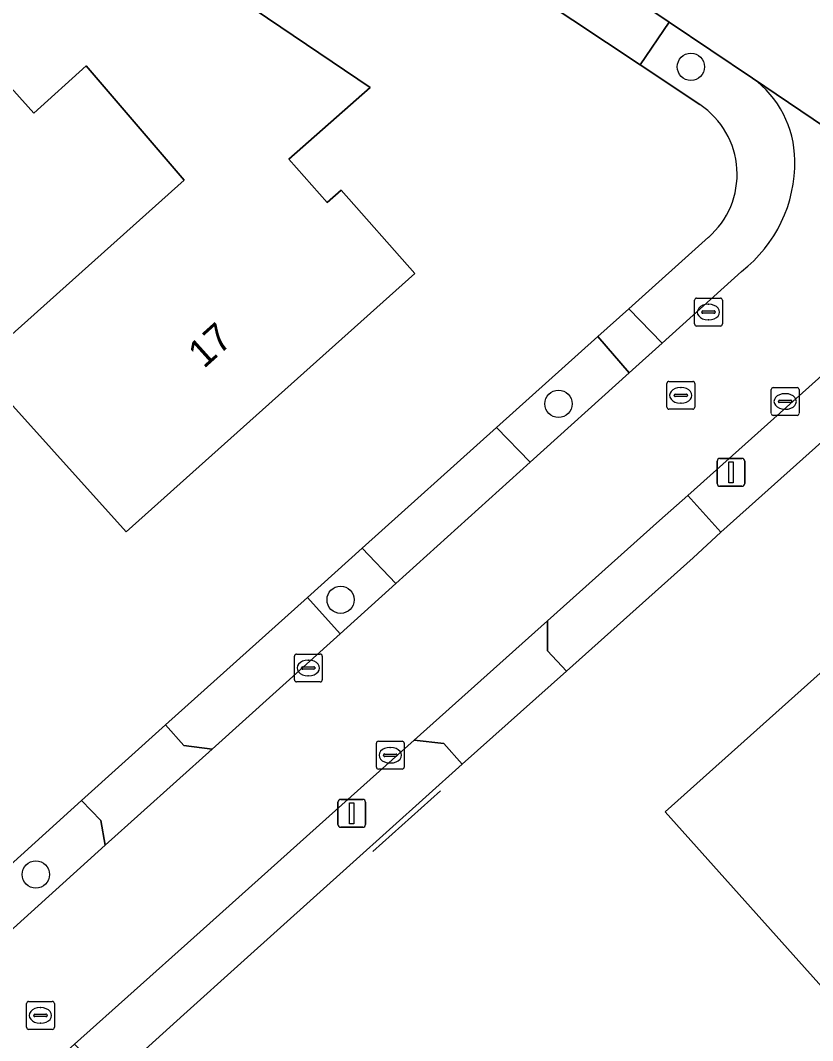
# Model space of a CAD drawing. Extents: x 163266 to 164362, y 381528 to 382286.
# Drawn here: x 163999.37 to 164027.8, y 381843.46 to 381880.07 of the extents above; entities that cross this region are included whole.
import ezdxf

# ---------------------------------------------------------------- set-up
doc = ezdxf.new("R2010")
doc.units = 0
for name, color, linetype in [('IMGEO_Boom', 7, 'Continuous'), ('IMGEO_Erf', 7, 'Continuous'), ('IMGEO_Groenvoorziening', 7, 'Continuous'), ('IMGEO_Hek', 7, 'Continuous'), ('IMGEO_Kolk', 7, 'Continuous'), ('IMGEO_Lichtmast', 7, 'Continuous'), ('IMGEO_Pand', 7, 'Continuous'), ('IMGEO_Pand_nummerreeks', 7, 'Continuous'), ('IMGEO_Rijbaan_lokaal_open', 7, 'Continuous'), ('IMGEO_Rioolput', 7, 'Continuous'), ('IMGEO_Voetpad_halfverhard', 7, 'Continuous'), ('IMGEO_Voetpad_open', 7, 'Continuous')]:
    doc.layers.add(name, color=color, linetype=linetype)

msp = doc.modelspace()

# ---------------------------------------------------------------- linework, layer by layer
at = {"layer": 'IMGEO_Boom'}
for centre in [(164023.434, 381878.405), (164018.683, 381866.309), (164010.865, 381859.278), (163999.93, 381849.416)]:
    msp.add_circle(centre, 0.489, dxfattribs=at)
at = {"layer": 'IMGEO_Erf'}
for points in [[(164023.757, 381877.048), (164021.609, 381878.481), (164017.994, 381880.891), (164016.88, 381881.641), (164004.426, 381889.991), (164000.285, 381892.756), (163999.021, 381893.687), (163929.416, 381832.861), (163943.921, 381816.693), (163948.755, 381811.304)], [(163995.657, 381846.77), (163996.816, 381847.775), (164001.565, 381852.077), (164004.578, 381854.784), (164009.675, 381859.363), (164011.636, 381861.124), (164016.456, 381865.455), (164020.095, 381868.724), (164021.208, 381869.724), (164024.059, 381872.285)], [(164032.089, 381868.482), (164024.506, 381861.698), (164023.513, 381860.781), (164018.964, 381856.717), (164015.222, 381853.377), (164011.317, 381849.862), (164007.28, 381846.23), (164005.236, 381844.39), (164002.603, 381842.006), (163996.129, 381836.145), (163993.15, 381833.516), (163988.909, 381829.691), (163987.827, 381828.705), (163977.86, 381819.863), (163977.933, 381819.715), (163968.392, 381811.087), (163967.388, 381810.18), (163960.895, 381804.406)]]:
    msp.add_lwpolyline(points, dxfattribs=at)
for points in [[(164003.17, 381861.72), (163997.803, 381867.67), (164005.249, 381874.338), (164001.739, 381878.437), (163999.856, 381876.747), (163995.833, 381881.231), (164000.469, 381885.413), (164011.921, 381877.668), (164009.01, 381875.086), (164010.379, 381873.532), (164010.889, 381873.982), (164013.525, 381870.99)], [(164022.506, 381851.666), (164034.418, 381862.323), (164040.335, 381855.737), (164028.428, 381845.055)]]:
    msp.add_lwpolyline(points, close=True, dxfattribs=at)
msp.add_arc((164022.092, 381874.551), 3.001, 310.9517, 56.3043, dxfattribs=at)
at = {"layer": 'IMGEO_Groenvoorziening'}
for points in [[(164025.646, 381878.003), (164022.652, 381880.012), (164021.609, 381878.481), (164023.757, 381877.048)], [(164024.059, 381872.285), (164021.208, 381869.724), (164022.399, 381868.488), (164025.25, 381871.061)], [(164030.291, 381869.269), (164023.318, 381863.024), (164024.506, 381861.698), (164032.089, 381868.482)]]:
    msp.add_lwpolyline(points, dxfattribs=at)
for points in [[(164020.095, 381868.724), (164016.456, 381865.455), (164017.67, 381864.218), (164021.224, 381867.427)], [(164012.841, 381859.859), (164011.636, 381861.124), (164009.675, 381859.363), (164010.847, 381858.058)], [(164002.418, 381850.471), (164002.258, 381851.352), (164001.565, 381852.077), (163996.816, 381847.775), (163997.98, 381846.456)]]:
    msp.add_lwpolyline(points, close=True, dxfattribs=at)
for centre, radius, start, end in [((164023.475, 381875.024), 3.686, 0.5272, 53.9182), ((164022.092, 381874.551), 3.001, 310.9517, 56.3043), ((164022.214, 381874.968), 4.948, 307.8517, 1.0426)]:
    msp.add_arc(centre, radius, start, end, dxfattribs=at)
at = {"layer": 'IMGEO_Hek'}
msp.add_lwpolyline([(164012.02, 381850.245), (164014.445, 381852.423)], dxfattribs=at)
at = {"layer": 'IMGEO_Kolk'}
for p, q in [((164023.563, 381869.176), (164023.563, 381870.028)), ((164023.638, 381870.102), (164024.49, 381870.102)), ((164024.564, 381870.028), (164024.564, 381869.176)), ((164023.865, 381869.645), (164024.263, 381869.645)), ((164024.051, 381869.882), (164024.076, 381869.882)), ((164023.822, 381869.596), (164023.822, 381869.608)), ((164024.26, 381869.559), (164023.862, 381869.559)), ((164024.074, 381869.322), (164024.049, 381869.322)), ((164024.306, 381869.608), (164024.306, 381869.596)), ((164024.49, 381869.102), (164023.638, 381869.102)), ((164026.315, 381865.968), (164026.315, 381866.82)), ((164026.39, 381866.894), (164027.242, 381866.894)), ((164027.316, 381866.82), (164027.316, 381865.968)), ((164026.574, 381866.388), (164026.574, 381866.4)), ((164027.012, 381866.351), (164026.614, 381866.351)), ((164026.617, 381866.437), (164027.015, 381866.437)), ((164026.803, 381866.674), (164026.828, 381866.674)), ((164027.058, 381866.4), (164027.058, 381866.388)), ((164026.826, 381866.114), (164026.801, 381866.114)), ((164027.242, 381865.894), (164026.39, 381865.894)), ((164009.206, 381856.402), (164009.206, 381857.254)), ((164009.281, 381857.328), (164010.133, 381857.328)), ((164010.207, 381857.254), (164010.207, 381856.402)), ((164009.465, 381856.822), (164009.465, 381856.834)), ((164009.508, 381856.871), (164009.906, 381856.871)), ((164009.694, 381857.108), (164009.719, 381857.108)), ((164009.949, 381856.834), (164009.949, 381856.822)), ((164009.903, 381856.785), (164009.505, 381856.785)), ((164009.717, 381856.548), (164009.692, 381856.548)), ((164010.133, 381856.328), (164009.281, 381856.328)), ((164012.147, 381853.272), (164012.147, 381854.124)), ((164012.222, 381854.198), (164013.074, 381854.198)), ((164012.635, 381853.978), (164012.66, 381853.978)), ((164013.148, 381854.124), (164013.148, 381853.272)), ((164012.406, 381853.692), (164012.406, 381853.704)), ((164012.844, 381853.655), (164012.446, 381853.655)), ((164012.449, 381853.741), (164012.847, 381853.741)), ((164012.89, 381853.704), (164012.89, 381853.692)), ((164013.074, 381853.198), (164012.222, 381853.198)), ((164012.658, 381853.418), (164012.633, 381853.418))]:
    msp.add_line(p, q, dxfattribs=at)
for points in [[(164023.563, 381869.176), (164023.563, 381870.028)], [(164023.638, 381870.102), (164024.49, 381870.102)], [(164024.564, 381870.028), (164024.564, 381869.176)], [(164024.49, 381869.102), (164023.638, 381869.102)], [(164026.315, 381865.968), (164026.315, 381866.82)], [(164026.39, 381866.894), (164027.242, 381866.894)], [(164027.316, 381866.82), (164027.316, 381865.968)], [(164027.242, 381865.894), (164026.39, 381865.894)], [(164009.206, 381856.402), (164009.206, 381857.254)], [(164009.281, 381857.328), (164010.133, 381857.328)], [(164010.207, 381857.254), (164010.207, 381856.402)], [(164010.133, 381856.328), (164009.281, 381856.328)], [(164012.147, 381853.272), (164012.147, 381854.124)], [(164012.222, 381854.198), (164013.074, 381854.198)], [(164013.148, 381854.124), (164013.148, 381853.272)], [(164013.074, 381853.198), (164012.222, 381853.198)]]:
    msp.add_lwpolyline(points, dxfattribs=at)
for centre, radius, start, end in [((164023.64, 381870.026), 0.0765, 91.552, 178.448), ((164023.64, 381870.026), 0.0765, 91.552, 178.448), ((164024.488, 381870.026), 0.0765, 1.552, 88.448), ((164024.488, 381870.026), 0.0765, 1.552, 88.448), ((164023.862, 381869.605), 0.0403, 85.8775, 175.7526), ((164024.267, 381869.607), 0.0386, 1.7309, 96.639), ((164023.859, 381869.595), 0.0366, 178.938, 274.7102), ((164024.263, 381869.602), 0.043, 264.8664, 352.4533), ((164023.64, 381869.178), 0.0765, 181.552, 268.448), ((164023.64, 381869.178), 0.0765, 181.552, 268.448), ((164024.488, 381869.178), 0.0765, 271.552, 358.448), ((164024.488, 381869.178), 0.0765, 271.552, 358.448), ((164026.392, 381866.818), 0.0765, 91.552, 178.448), ((164026.392, 381866.818), 0.0765, 91.552, 178.448), ((164027.24, 381866.818), 0.0765, 1.552, 88.448), ((164027.24, 381866.818), 0.0765, 1.552, 88.448), ((164026.614, 381866.397), 0.0403, 85.8775, 175.7526), ((164026.611, 381866.387), 0.0366, 178.938, 274.7102), ((164027.015, 381866.394), 0.043, 264.8664, 352.4533), ((164027.019, 381866.399), 0.0386, 1.7309, 96.639), ((164026.392, 381865.97), 0.0765, 181.552, 268.448), ((164026.392, 381865.97), 0.0765, 181.552, 268.448), ((164027.24, 381865.97), 0.0765, 271.552, 358.448), ((164027.24, 381865.97), 0.0765, 271.552, 358.448), ((164009.283, 381857.252), 0.0765, 91.552, 178.448), ((164009.283, 381857.252), 0.0765, 91.552, 178.448), ((164010.131, 381857.252), 0.0765, 1.552, 88.448), ((164010.131, 381857.252), 0.0765, 1.552, 88.448), ((164009.505, 381856.831), 0.0403, 85.8775, 175.7526), ((164009.91, 381856.833), 0.0386, 1.7309, 96.639), ((164009.502, 381856.821), 0.0366, 178.938, 274.7102), ((164009.906, 381856.828), 0.043, 264.8664, 352.4533), ((164009.283, 381856.404), 0.0765, 181.552, 268.448), ((164009.283, 381856.404), 0.0765, 181.552, 268.448), ((164010.131, 381856.404), 0.0765, 271.552, 358.448), ((164010.131, 381856.404), 0.0765, 271.552, 358.448), ((164012.224, 381854.122), 0.0765, 91.552, 178.448), ((164012.224, 381854.122), 0.0765, 91.552, 178.448), ((164013.072, 381854.122), 0.0765, 1.552, 88.448), ((164013.072, 381854.122), 0.0765, 1.552, 88.448), ((164012.446, 381853.701), 0.0403, 85.8775, 175.7526), ((164012.443, 381853.691), 0.0366, 178.938, 274.7102), ((164012.847, 381853.698), 0.043, 264.8664, 352.4533), ((164012.851, 381853.703), 0.0386, 1.7309, 96.639), ((164012.224, 381853.274), 0.0765, 181.552, 268.448), ((164012.224, 381853.274), 0.0765, 181.552, 268.448), ((164013.072, 381853.274), 0.0765, 271.552, 358.448), ((164013.072, 381853.274), 0.0765, 271.552, 358.448)]:
    msp.add_arc(centre, radius, start, end, dxfattribs=at)
for centre, major_axis, ratio, start_param, end_param in [((164024.05, 381869.602), (-0.387, 0.002), 0.722429, 4.712389, 7.853982), ((164024.075, 381869.602), (-0.39, 0.002), 0.717154, 1.570796, 4.712389), ((164026.802, 381866.394), (-0.387, 0.002), 0.722429, 4.712389, 7.853982), ((164026.827, 381866.394), (-0.39, 0.002), 0.717154, 1.570796, 4.712389), ((164009.693, 381856.828), (-0.387, 0.002), 0.722429, 4.712389, 7.853982), ((164009.718, 381856.828), (-0.39, 0.002), 0.717154, 1.570796, 4.712389), ((164012.634, 381853.698), (-0.387, 0.002), 0.722429, 4.712389, 7.853982), ((164012.659, 381853.698), (-0.39, 0.002), 0.717154, 1.570796, 4.712389)]:
    msp.add_ellipse(centre, major_axis=major_axis, ratio=ratio, start_param=start_param, end_param=end_param, dxfattribs=at)
at = {"layer": 'IMGEO_Lichtmast'}
for p, q in [((164024.376, 381863.449), (164024.376, 381864.249)), ((164024.376, 381864.249), (164024.376, 381863.449)), ((164024.476, 381864.349), (164025.266, 381864.349)), ((164025.266, 381864.349), (164024.476, 381864.349)), ((164025.366, 381864.249), (164025.366, 381863.449)), ((164025.366, 381863.449), (164025.366, 381864.249)), ((164025.266, 381863.349), (164024.476, 381863.349)), ((164024.476, 381863.349), (164025.266, 381863.349)), ((164010.869, 381852.111), (164011.659, 381852.111)), ((164011.659, 381852.111), (164010.869, 381852.111)), ((164010.769, 381851.211), (164010.769, 381852.011)), ((164010.769, 381852.011), (164010.769, 381851.211)), ((164011.759, 381852.011), (164011.759, 381851.211)), ((164011.759, 381851.211), (164011.759, 381852.011)), ((164011.659, 381851.111), (164010.869, 381851.111)), ((164010.869, 381851.111), (164011.659, 381851.111))]:
    msp.add_line(p, q, dxfattribs=at)
for points in [[(164024.796, 381864.224), (164024.946, 381864.224), (164024.946, 381863.474), (164024.796, 381863.474), (164024.796, 381864.224)], [(164011.189, 381851.986), (164011.339, 381851.986), (164011.339, 381851.236), (164011.189, 381851.236), (164011.189, 381851.986)]]:
    msp.add_lwpolyline(points, dxfattribs=at)
for centre, start, end in [((164024.476, 381864.249), 90, 180), ((164024.476, 381864.249), 90, 180), ((164025.266, 381864.249), 0, 90), ((164025.266, 381864.249), 360, 90), ((164024.476, 381863.449), 180, 270), ((164024.476, 381863.449), 180, 270), ((164025.266, 381863.449), 270, 0), ((164025.266, 381863.449), 270, 0), ((164010.869, 381852.011), 90, 180), ((164010.869, 381852.011), 90, 180), ((164011.659, 381852.011), 0, 90), ((164011.659, 381852.011), 360, 90), ((164010.869, 381851.211), 180, 270), ((164010.869, 381851.211), 180, 270), ((164011.659, 381851.211), 270, 0), ((164011.659, 381851.211), 270, 0)]:
    msp.add_arc(centre, 0.1, start, end, dxfattribs=at)
at = {"layer": 'IMGEO_Pand'}
for points in [[(164003.17, 381861.72), (164013.525, 381870.99), (164010.889, 381873.982), (164010.379, 381873.532), (164009.01, 381875.086), (164011.921, 381877.668), (164000.469, 381885.413), (163995.833, 381881.231), (163999.856, 381876.747), (164001.739, 381878.437), (164005.249, 381874.338), (163997.803, 381867.67)], [(164028.428, 381845.055), (164040.335, 381855.737), (164034.418, 381862.323), (164022.506, 381851.666)]]:
    msp.add_lwpolyline(points, close=True, dxfattribs=at)
at = {"layer": 'IMGEO_Rijbaan_lokaal_open'}
for points in [[(163998.571, 381897.023), (163999, 381896.735), (163999.804, 381896.196), (163999.429, 381895.594), (163999.796, 381895.348), (164001.074, 381894.49), (164006.028, 381891.166), (164017.924, 381883.184), (164019.023, 381882.448), (164022.652, 381880.012), (164025.646, 381878.003), (164036.893, 381870.385), (164038.576, 381869.252), (164061.479, 381853.831), (164067.085, 381850.057), (164074.222, 381845.198), (164075.369, 381844.441), (164083.195, 381839.066), (164084.215, 381838.47)], [(164036.893, 381870.385), (164025.646, 381878.003)], [(164025.25, 381871.061), (164022.399, 381868.488), (164021.224, 381867.427), (164017.67, 381864.218), (164012.841, 381859.859), (164010.847, 381858.058), (164006.252, 381853.91), (164002.418, 381850.471), (163997.98, 381846.456), (163996.879, 381845.395), (163993.203, 381842.104), (163989.118, 381838.447), (163984.024, 381833.886), (163978.103, 381828.584), (163977.1, 381827.686), (163974.775, 381825.604), (163971.984, 381823.105), (163967.775, 381819.337), (163963.088, 381815.14), (163962.055, 381814.215), (163958.417, 381810.957), (163956.533, 381809.27)], [(163966.045, 381811.633), (163967.113, 381812.548), (163968.97, 381814.303), (163976.655, 381821.186), (163986.562, 381830.06), (163987.615, 381831.052), (163991.405, 381834.479), (163995.302, 381837.956), (164001.317, 381843.33), (164005.596, 381847.153), (164010.686, 381851.711), (164013.509, 381854.239), (164018.289, 381858.52), (164022.308, 381862.12), (164023.318, 381863.024), (164030.291, 381869.269)]]:
    msp.add_lwpolyline(points, dxfattribs=at)
for centre, radius, start, end in [((164023.475, 381875.024), 3.686, 0.5272, 53.9182), ((164022.214, 381874.968), 4.948, 307.8517, 1.0426)]:
    msp.add_arc(centre, radius, start, end, dxfattribs=at)
at = {"layer": 'IMGEO_Rioolput'}
for p, q in [((164022.645, 381867.115), (164023.497, 381867.115)), ((164022.57, 381866.189), (164022.57, 381867.041)), ((164023.058, 381866.895), (164023.083, 381866.895)), ((164023.571, 381867.041), (164023.571, 381866.189)), ((164022.829, 381866.609), (164022.829, 381866.621)), ((164023.267, 381866.572), (164022.869, 381866.572)), ((164022.872, 381866.658), (164023.27, 381866.658)), ((164023.313, 381866.621), (164023.313, 381866.609)), ((164023.497, 381866.115), (164022.645, 381866.115)), ((164023.081, 381866.335), (164023.056, 381866.335)), ((163999.593, 381843.933), (163999.593, 381844.785)), ((163999.668, 381844.859), (164000.52, 381844.859)), ((164000.594, 381844.785), (164000.594, 381843.933)), ((163999.895, 381844.402), (164000.293, 381844.402)), ((164000.081, 381844.639), (164000.106, 381844.639)), ((163999.852, 381844.353), (163999.852, 381844.365)), ((164000.29, 381844.316), (163999.892, 381844.316)), ((164000.104, 381844.079), (164000.079, 381844.079)), ((164000.336, 381844.365), (164000.336, 381844.353)), ((164000.52, 381843.859), (163999.668, 381843.859))]:
    msp.add_line(p, q, dxfattribs=at)
for points in [[(164022.645, 381867.115), (164023.497, 381867.115)], [(164022.57, 381866.189), (164022.57, 381867.041)], [(164023.571, 381867.041), (164023.571, 381866.189)], [(164023.497, 381866.115), (164022.645, 381866.115)], [(163999.593, 381843.933), (163999.593, 381844.785)], [(163999.668, 381844.859), (164000.52, 381844.859)], [(164000.594, 381844.785), (164000.594, 381843.933)], [(164000.52, 381843.859), (163999.668, 381843.859)]]:
    msp.add_lwpolyline(points, dxfattribs=at)
for centre, radius, start, end in [((164022.647, 381867.039), 0.0765, 91.552, 178.448), ((164022.647, 381867.039), 0.0765, 91.552, 178.448), ((164023.495, 381867.039), 0.0765, 1.552, 88.448), ((164023.495, 381867.039), 0.0765, 1.552, 88.448), ((164022.869, 381866.618), 0.0403, 85.8775, 175.7526), ((164022.866, 381866.608), 0.0366, 178.938, 274.7102), ((164023.27, 381866.615), 0.043, 264.8664, 352.4533), ((164023.274, 381866.62), 0.0386, 1.7309, 96.639), ((164022.647, 381866.191), 0.0765, 181.552, 268.448), ((164022.647, 381866.191), 0.0765, 181.552, 268.448), ((164023.495, 381866.191), 0.0765, 271.552, 358.448), ((164023.495, 381866.191), 0.0765, 271.552, 358.448), ((163999.67, 381844.783), 0.0765, 91.552, 178.448), ((163999.67, 381844.783), 0.0765, 91.552, 178.448), ((164000.518, 381844.783), 0.0765, 1.552, 88.448), ((164000.518, 381844.783), 0.0765, 1.552, 88.448), ((163999.892, 381844.362), 0.0403, 85.8775, 175.7526), ((164000.297, 381844.364), 0.0386, 1.7309, 96.639), ((163999.889, 381844.352), 0.0366, 178.938, 274.7102), ((164000.293, 381844.359), 0.043, 264.8664, 352.4533), ((163999.67, 381843.935), 0.0765, 181.552, 268.448), ((163999.67, 381843.935), 0.0765, 181.552, 268.448), ((164000.518, 381843.935), 0.0765, 271.552, 358.448), ((164000.518, 381843.935), 0.0765, 271.552, 358.448)]:
    msp.add_arc(centre, radius, start, end, dxfattribs=at)
for centre, major_axis, ratio, start_param, end_param in [((164023.057, 381866.615), (-0.387, 0.002), 0.722429, 4.712389, 7.853982), ((164023.082, 381866.615), (-0.39, 0.002), 0.717154, 1.570796, 4.712389), ((164000.08, 381844.359), (-0.387, 0.002), 0.722429, 4.712389, 7.853982), ((164000.105, 381844.359), (-0.39, 0.002), 0.717154, 1.570796, 4.712389)]:
    msp.add_ellipse(centre, major_axis=major_axis, ratio=ratio, start_param=start_param, end_param=end_param, dxfattribs=at)
at = {"layer": 'IMGEO_Voetpad_halfverhard'}
msp.add_lwpolyline([(164019.023, 381882.448), (164017.994, 381880.891), (164021.609, 381878.481), (164022.652, 381880.012)], close=True, dxfattribs=at)
at = {"layer": 'IMGEO_Voetpad_open'}
for points in [[(164021.208, 381869.724), (164020.095, 381868.724), (164021.224, 381867.427), (164022.399, 381868.488)], [(164017.67, 381864.218), (164016.456, 381865.455), (164011.636, 381861.124), (164012.841, 381859.859)], [(164023.513, 381860.781), (164024.506, 381861.698), (164023.318, 381863.024), (164022.308, 381862.12), (164018.289, 381858.52), (164018.289, 381857.449), (164018.964, 381856.717)], [(164010.847, 381858.058), (164009.675, 381859.363), (164004.578, 381854.784), (164005.238, 381854.043), (164006.252, 381853.91)], [(164013.509, 381854.239), (164014.564, 381854.114), (164015.222, 381853.377), (164018.964, 381856.717), (164018.289, 381857.449), (164018.289, 381858.52)], [(164001.565, 381852.077), (164002.258, 381851.352), (164002.418, 381850.471), (164006.252, 381853.91), (164005.238, 381854.043), (164004.578, 381854.784)], [(164011.317, 381849.862), (164015.222, 381853.377), (164014.564, 381854.114), (164013.509, 381854.239), (164010.686, 381851.711), (164005.596, 381847.153), (164001.317, 381843.33), (164002.603, 381842.006), (164005.236, 381844.39), (164007.28, 381846.23)]]:
    msp.add_lwpolyline(points, close=True, dxfattribs=at)

# ---------------------------------------------------------------- texts
at = {"layer": 'IMGEO_Pand_nummerreeks'}
msp.add_text('17', height=1, rotation=41.9961, dxfattribs=at).set_placement((164005.956, 381867.55))

doc.saveas('drawing.dxf')
